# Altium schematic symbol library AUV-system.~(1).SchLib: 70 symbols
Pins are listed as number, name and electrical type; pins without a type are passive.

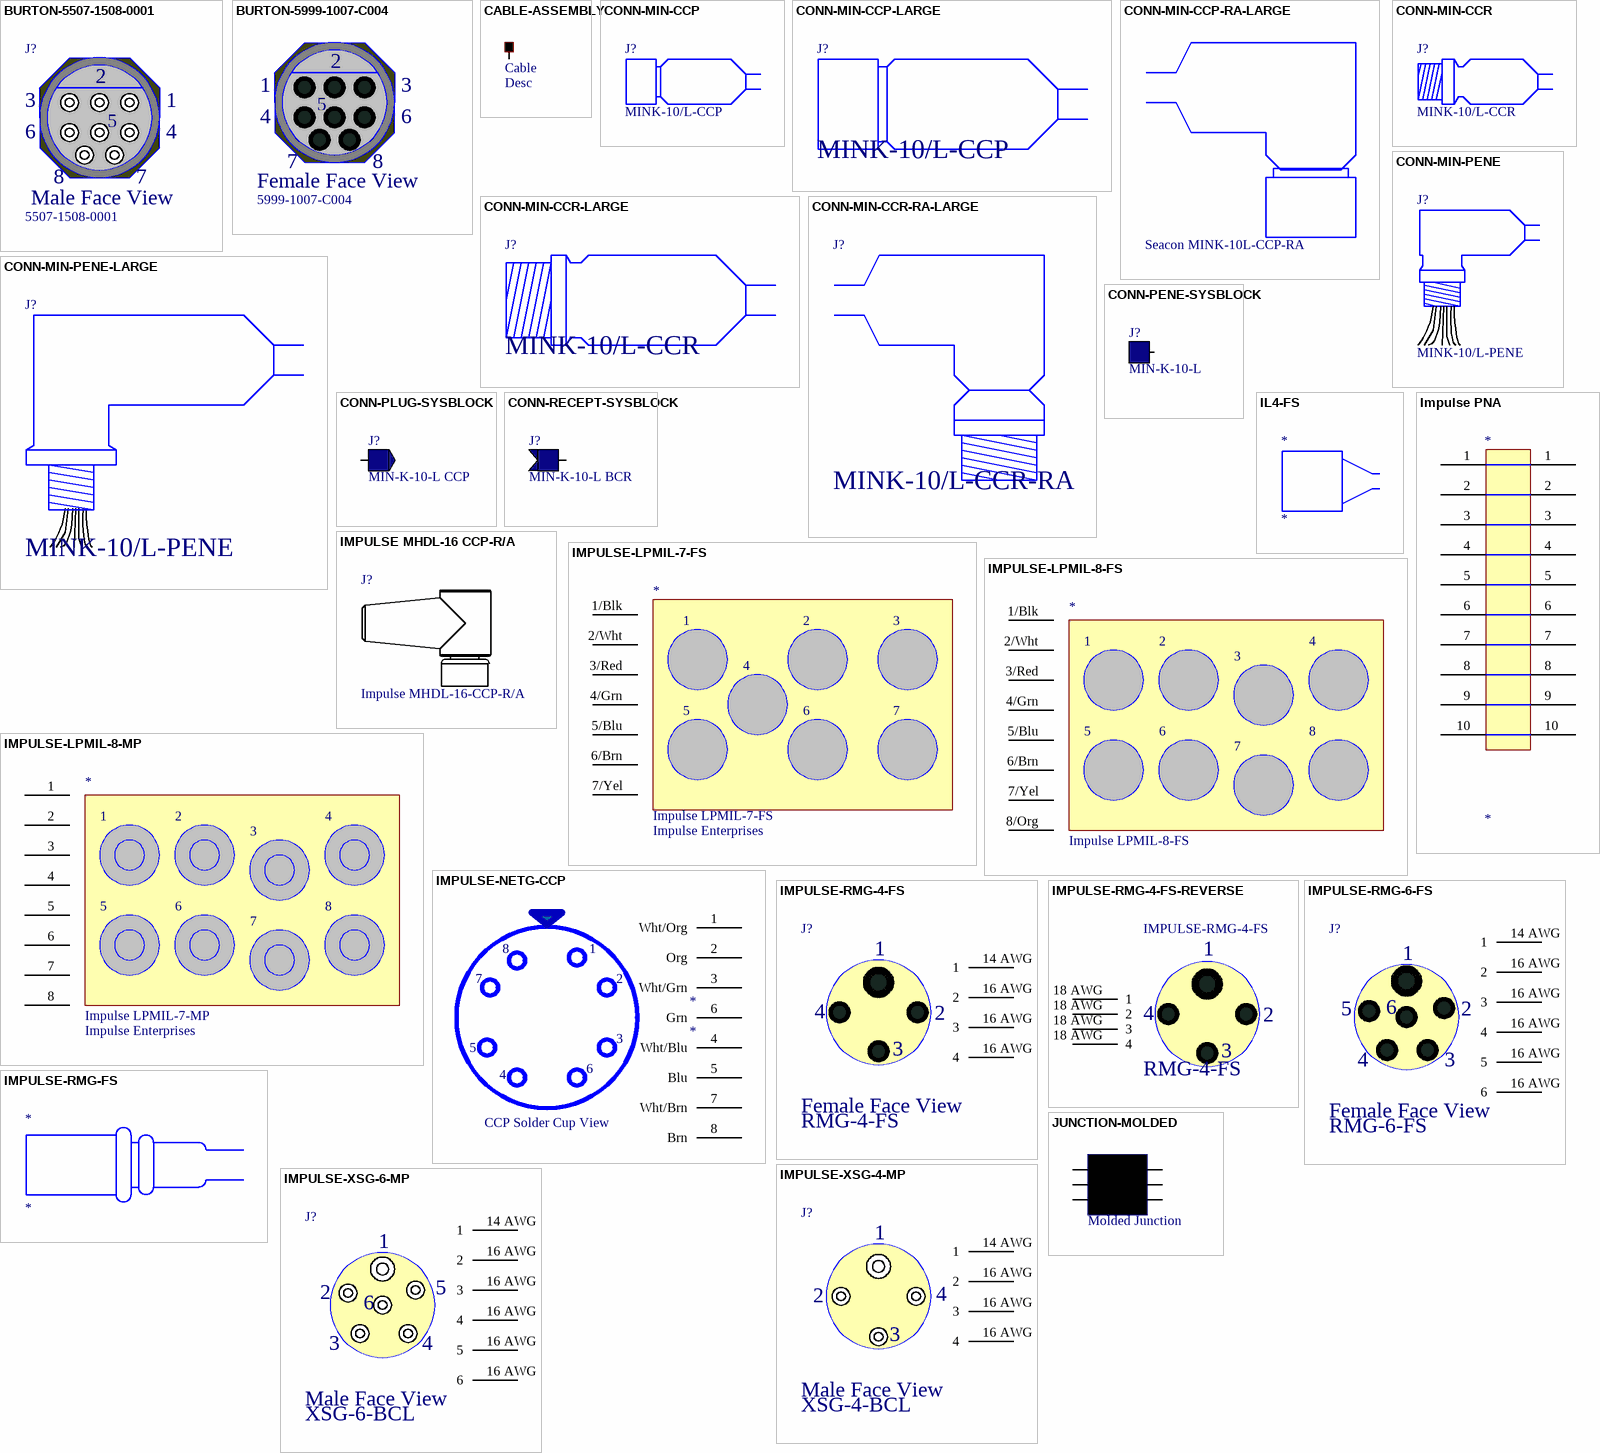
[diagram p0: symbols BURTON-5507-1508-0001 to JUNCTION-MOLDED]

## BURTON-5507-1508-0001
designator J?, comment 5507-1508-0001
Burton 8 Pin Male BH Connector

## BURTON-5999-1007-C004
designator J?, comment 5999-1007-C004
Burton 8 Socket Female IL Connector

## CABLE-ASSEMBLY
designator J?, comment Cable  DescSheet: Desc
Cable Assembly
pins: 0 "Pointer"

## CONN-MIN-CCP
designator J?, comment MINK-10/L-CCP
Seacon MIN Connector CCP

## CONN-MIN-CCP-LARGE
designator J?, comment MINK-10/L-CCP
Seacon MIN Connector CCP

## CONN-MIN-CCP-RA-LARGE
designator *, comment Seacon MINK-10L-CCP-RA

## CONN-MIN-CCR
designator J?, comment MINK-10/L-CCR
Seacon MIN Connector CCR

## CONN-MIN-CCR-LARGE
designator J?, comment MINK-10/L-CCR
Seacon MIN Connector CCR

## CONN-MIN-CCR-RA-LARGE
designator J?, comment MINK-10/L-CCR-RA
Seacon MIN Connector CCR Right Angle

## CONN-MIN-PENE
designator J?, comment MINK-10/L-PENE
Seacon MIN Penetrator

## CONN-MIN-PENE-LARGE
designator J?, comment MINK-10/L-PENE
Seacon MIN Penetrator

## CONN-PENE-SYSBLOCK
designator J?, comment MIN-K-10-L
Pene Symbol; Manufacturer: Seacon
pins: 0

## CONN-PLUG-SYSBLOCK
designator J?, comment MIN-K-10-L CCP
Plug Symbol; Manufacturer: Seacon
pins: 0

## CONN-RECEPT-SYSBLOCK
designator J?, comment MIN-K-10-L BCR
Recept Symbol; Manufacturer: Seacon
pins: 0

## IL4-FS
designator *

## IMPULSE MHDL-16 CCP-R/A
designator J?, comment Impulse MHDL-16-CCP-R/A

## Impulse PNA
designator *
Impulse 1''-14 PNA SS R/A Mold w/ 12x#16 Insert
pins: 1, 1, 2, 2, 3, 3, 4, 4, 5, 5, 6, 6, 7, 7, 8, 8, 9, 9, 10, 10

## IMPULSE-LPMIL-7-FS
designator *, comment Impulse LPMIL-7-FS  Vendor: Impulse Enterprises
pins: 1/Blk, 2/Wht 2, 3/Red 3, 4/Grn 4, 5/Blu 5, 6/Brn 6, 7/Yel 7

## IMPULSE-LPMIL-8-FS
designator *, comment Impulse LPMIL-8-FS
Impulse-8-FS Connector
pins: 1/Blk, 2/Wht 2, 3/Red 3, 4/Grn 4, 5/Blu 5, 6/Brn 6, 7/Yel 7, 8/Org 8

## IMPULSE-LPMIL-8-MP
designator *, comment Impulse LPMIL-7-MP  Vendor: Impulse Enterprises
Impulse LPMIL-8-MP Connector
pins: 1, 2, 3, 4, 5, 6, 7, 8

## IMPULSE-NETG-CCP
designator *
pins: 1 Wht/Org, 2 Org, 3 Wht/Grn, 4 Wht/Blu, 5 Blu, 6 Grn, 7 Wht/Brn, 8 Brn

## IMPULSE-RMG-4-FS
designator J?, comment RMG-4-FS
Impulse RMG Connector
pins: 14 AWG 1, 16 AWG 2, 16 AWG 3, 16 AWG 4

## IMPULSE-RMG-4-FS-REVERSE
designator IMPULSE-RMG-4-FS, comment RMG-4-FS
pins: 18 AWG 1, 18 AWG 2, 18 AWG 3, 18 AWG 4

## IMPULSE-RMG-6-FS
designator J?, comment RMG-6-FS
Impulse RMG Connector
pins: 14 AWG 1, 16 AWG 2, 16 AWG 3, 16 AWG 4, 16 AWG 5, 16 AWG 6

## IMPULSE-RMG-FS
designator *

## IMPULSE-XSG-4-MP
designator J?, comment XSG-4-BCL
Impulse XSG Connector; ManufPartNo: XSG-4-MP
pins: 14 AWG 1, 16 AWG 2, 16 AWG 3, 16 AWG 4

## IMPULSE-XSG-6-MP
designator J?, comment XSG-6-BCL
Impulse XSG Connector; ManufPartNo: XSG-6-MP
pins: 14 AWG 1, 16 AWG 2, 16 AWG 3, 16 AWG 4, 16 AWG 5, 16 AWG 6

## JUNCTION-MOLDED
designator J?, comment Molded Junction
pins: 1, 2, 3, 4, 5, 6

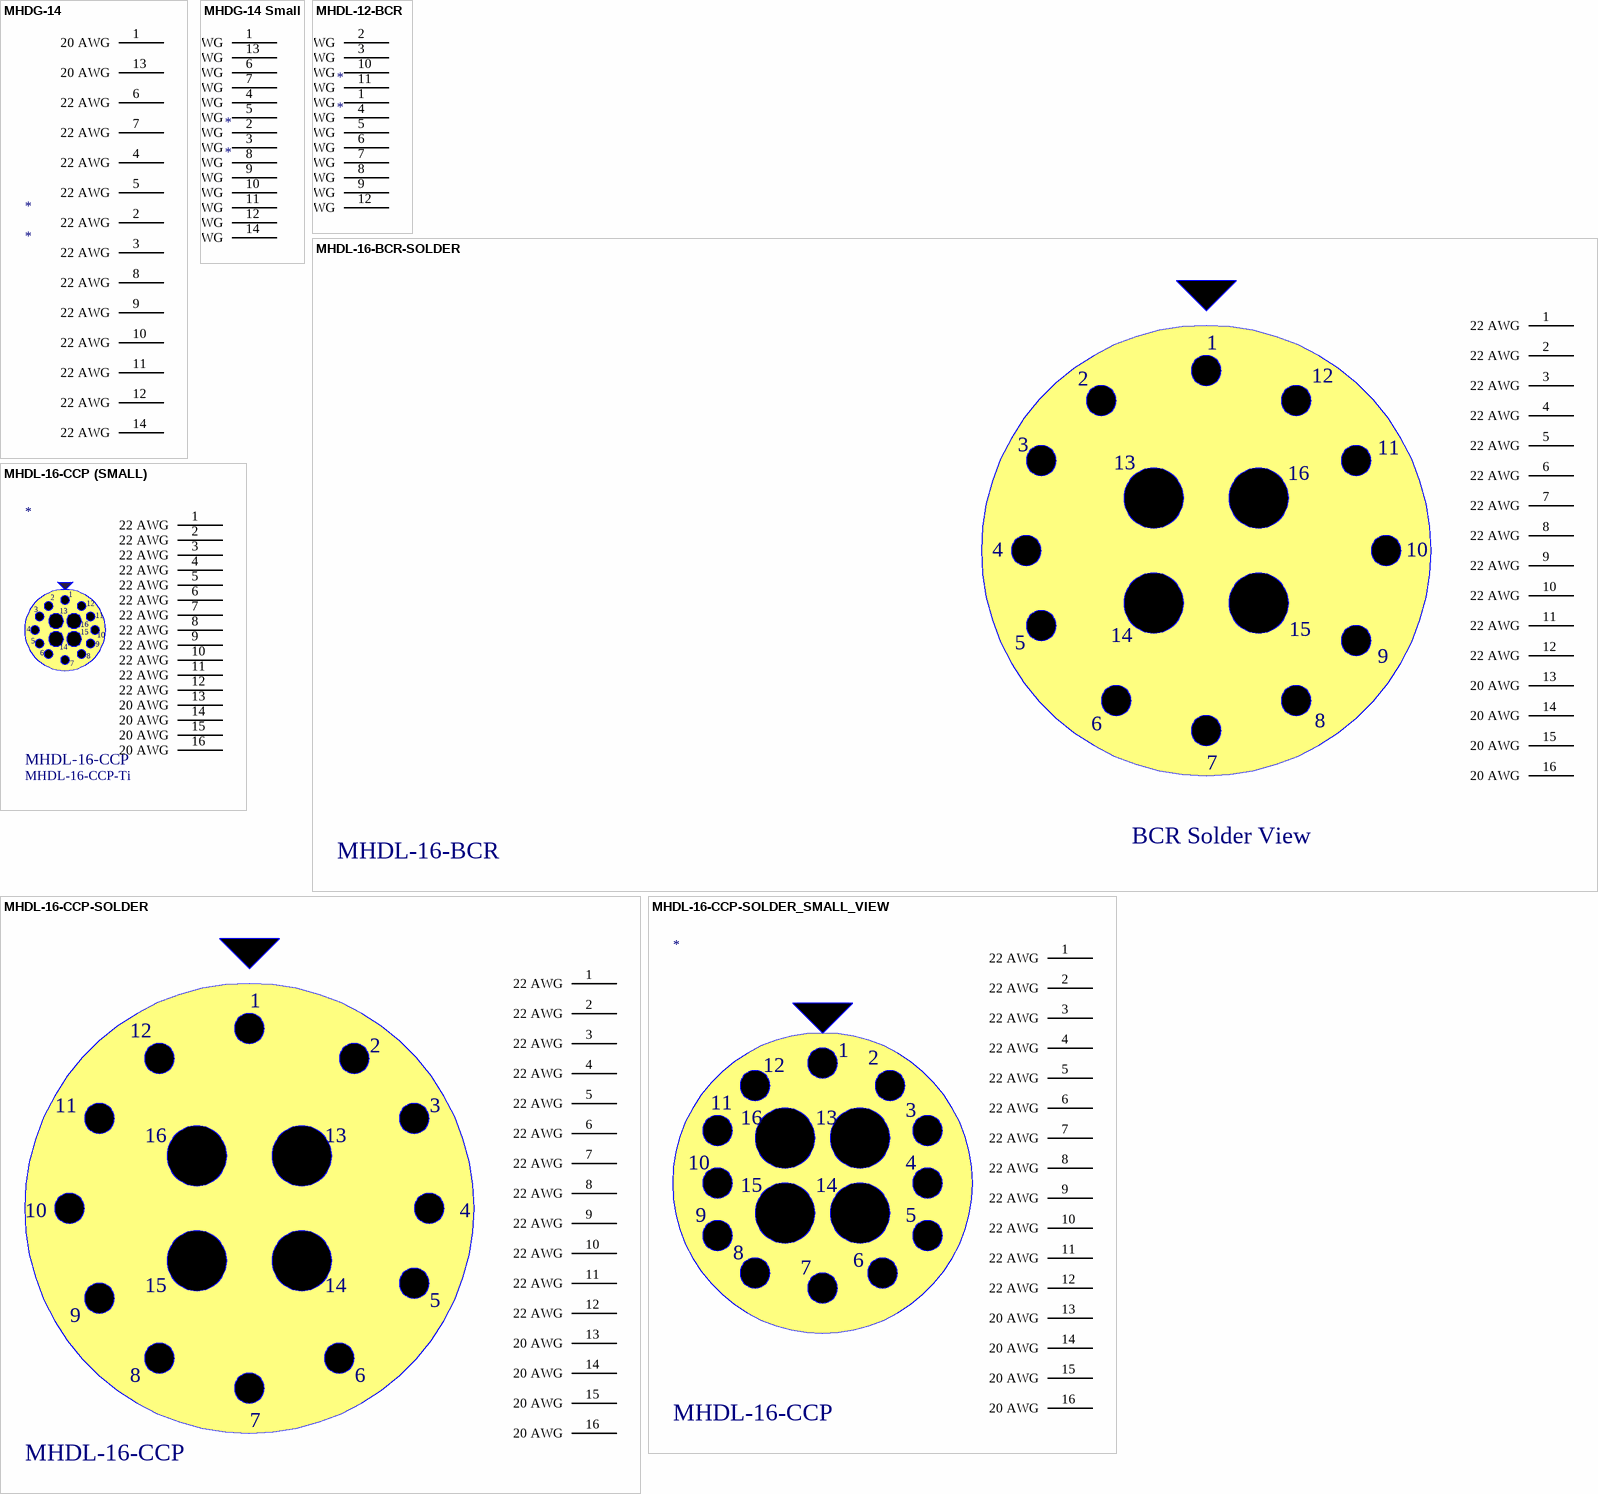
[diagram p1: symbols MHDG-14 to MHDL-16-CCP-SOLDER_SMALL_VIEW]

## MHDG-14
designator *
pins: 1 20 AWG, 2 22 AWG, 3 22 AWG, 4 22 AWG, 5 22 AWG, 6 22 AWG, 7 22 AWG, 8 22 AWG, 9 22 AWG, 10 22 AWG, 11 22 AWG, 12 22 AWG, 13 20 AWG, 14 22 AWG

## MHDG-14 Small
designator *
pins: 1 20 AWG, 2 22 AWG, 3 22 AWG, 4 22 AWG, 5 22 AWG, 6 22 AWG, 7 22 AWG, 8 22 AWG, 9 22 AWG, 10 22 AWG, 11 22 AWG, 12 22 AWG, 13 20 AWG, 14 22 AWG

## MHDL-12-BCR
designator *
Impulse MHDL12 BCR
pins: 1 22AWG, 2 16AWG, 3 16AWG, 4 22AWG, 5 22AWG, 6 22AWG, 7 22AWG, 8 22AWG, 9 22AWG, 10 16AWG, 11 16AWG, 12 22AWG

## MHDL-16-BCR-SOLDER
designator J?, comment MHDL-16-BCR
Impulse MHDL 16 BCR
pins: 1 22 AWG, 2 22 AWG, 3 22 AWG, 4 22 AWG, 5 22 AWG, 6 22 AWG, 7 22 AWG, 8 22 AWG, 9 22 AWG, 10 22 AWG, 11 22 AWG, 12 22 AWG, 13 20 AWG, 14 20 AWG, 15 20 AWG, 16 20 AWG

## MHDL-16-CCP (SMALL)
designator *, comment MHDL-16-CCP  ManufPartNo: MHDL-16-CCP-Ti
Impulse MHDL-16-CCP molded to C/F Falmat Cable
pins: 1 22 AWG, 2 22 AWG, 3 22 AWG, 4 22 AWG, 5 22 AWG, 6 22 AWG, 7 22 AWG, 8 22 AWG, 9 22 AWG, 10 22 AWG, 11 22 AWG, 12 22 AWG, 13 20 AWG, 14 20 AWG, 15 20 AWG, 16 20 AWG

## MHDL-16-CCP-SOLDER
designator J?, comment MHDL-16-CCP
Impulse MHDL 16 CCP
pins: 1 22 AWG, 2 22 AWG, 3 22 AWG, 4 22 AWG, 5 22 AWG, 6 22 AWG, 7 22 AWG, 8 22 AWG, 9 22 AWG, 10 22 AWG, 11 22 AWG, 12 22 AWG, 13 20 AWG, 14 20 AWG, 15 20 AWG, 16 20 AWG

## MHDL-16-CCP-SOLDER_SMALL_VIEW
designator *, comment MHDL-16-CCP
pins: 1 22 AWG, 2 22 AWG, 3 22 AWG, 4 22 AWG, 5 22 AWG, 6 22 AWG, 7 22 AWG, 8 22 AWG, 9 22 AWG, 10 22 AWG, 11 22 AWG, 12 22 AWG, 13 20 AWG, 14 20 AWG, 15 20 AWG, 16 20 AWG

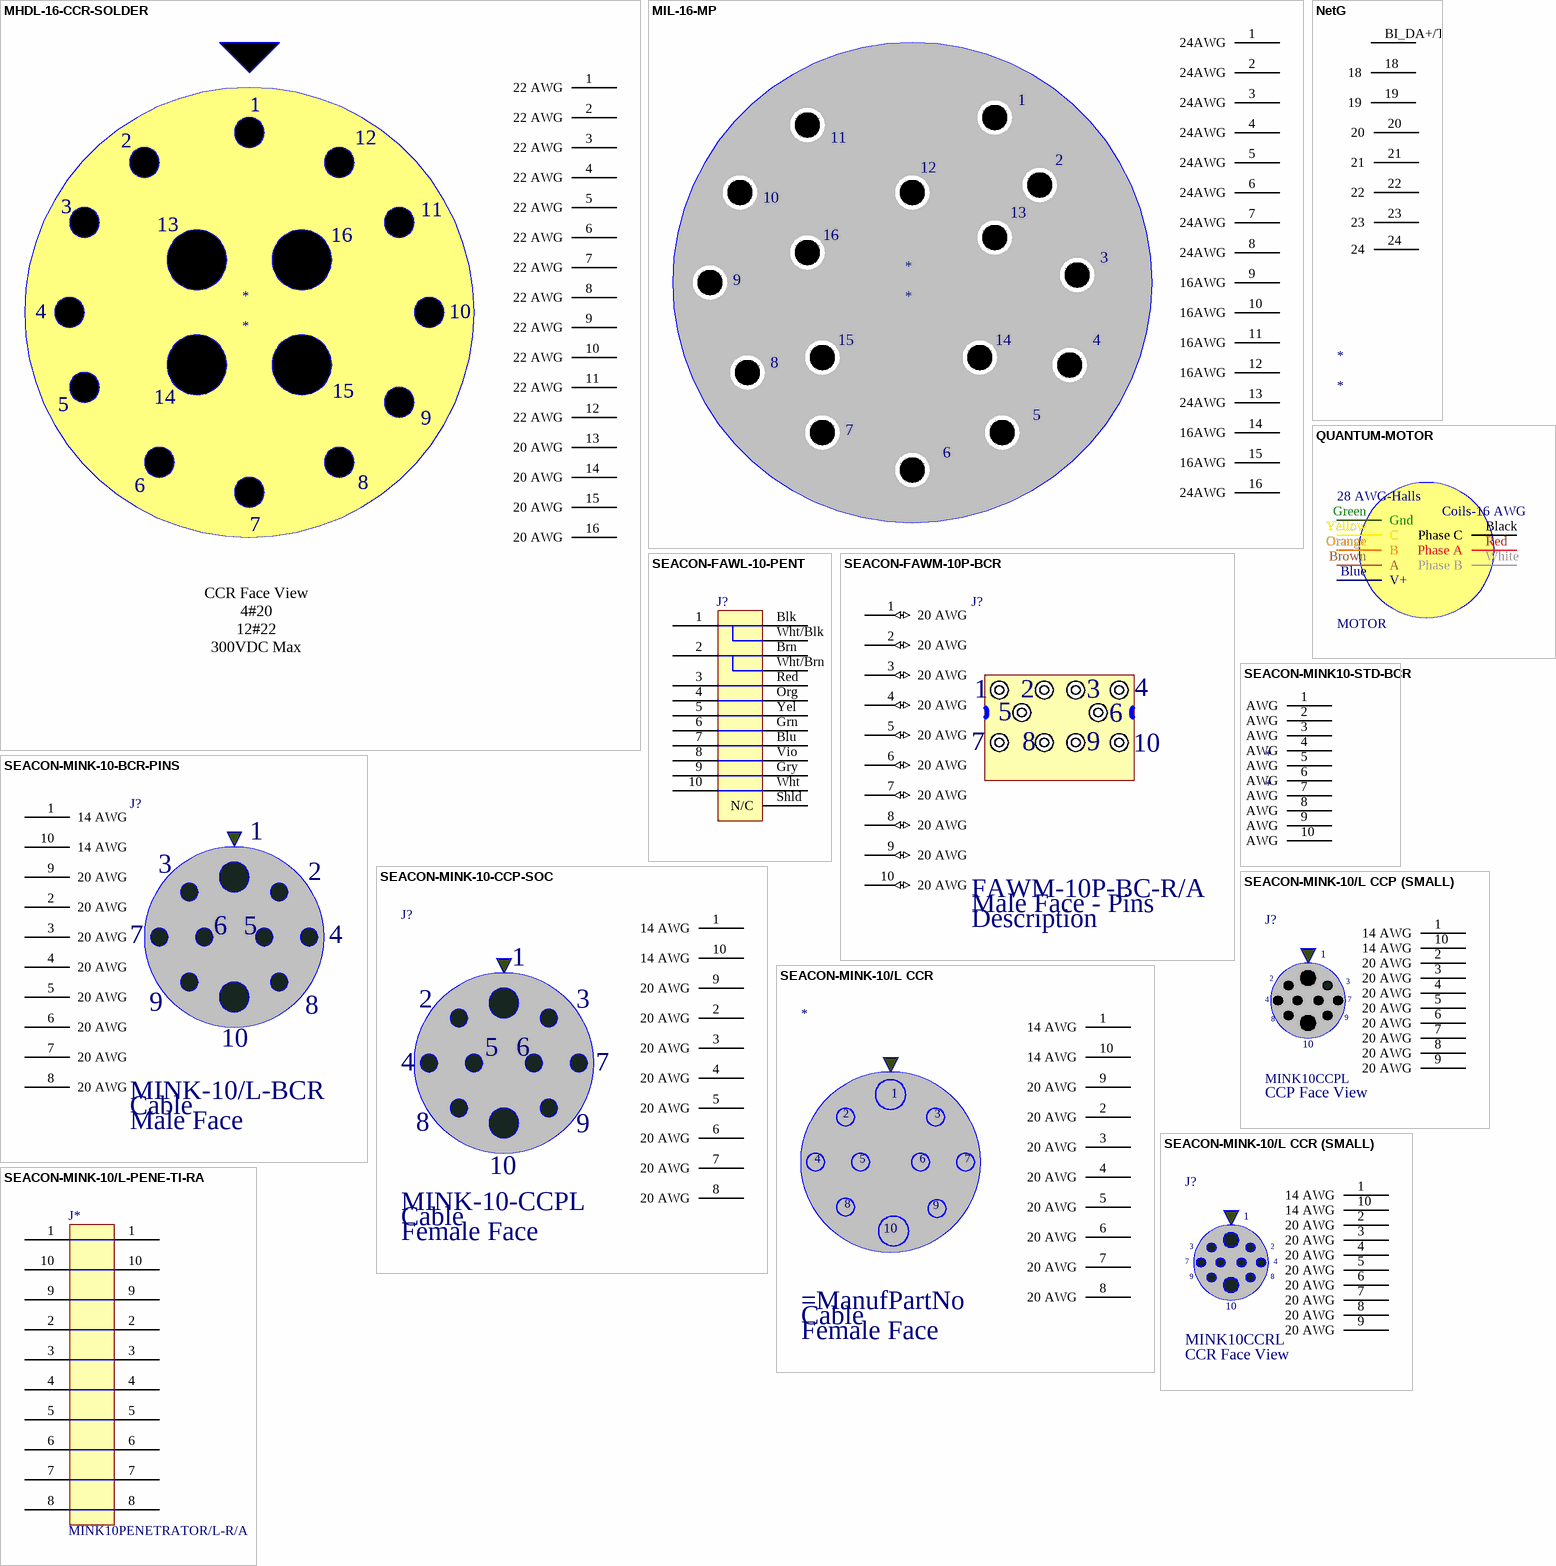
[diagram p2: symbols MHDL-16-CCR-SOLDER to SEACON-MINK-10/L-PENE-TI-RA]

## MHDL-16-CCR-SOLDER
designator *
pins: 1 22 AWG, 2 22 AWG, 3 22 AWG, 4 22 AWG, 5 22 AWG, 6 22 AWG, 7 22 AWG, 8 22 AWG, 9 22 AWG, 10 22 AWG, 11 22 AWG, 12 22 AWG, 13 20 AWG, 14 20 AWG, 15 20 AWG, 16 20 AWG

## MIL-16-MP
designator *
pins: 1 24AWG, 2 24AWG, 3 24AWG, 4 24AWG, 5 24AWG, 6 24AWG, 7 24AWG, 8 24AWG, 9 16AWG, 10 16AWG, 11 16AWG, 12 16AWG, 13 24AWG, 14 16AWG, 15 16AWG, 16 24AWG

## NetG
designator *
pins: 18, 19, 20, 21, 22, 23, 24, BI_DA+/TX+

## QUANTUM-MOTOR
designator ?, comment MOTOR
Quantum Motor
pins: Black Phase C (power), Blue V+ (power), Brown A (power), Green Gnd (power), Orange B (power), Red Phase A (power), White Phase B (power), Yellow C (power)

## SEACON-FAWL-10-PENT
designator J?
FAWL-10 Penetrator Molded onto Falmat #9835 Cable; Manufacturer: Seacon; ManufPartNo: FAWL-10-PENT
pins: 1, 2, 3, 4, 5, 6, 7, 8, 9, 10, Blk, Blu, Brn, Grn, Gry, Org, Red, Shld N/C, Vio, Wht, Wht/Blk, Wht/Brn, Yel

## SEACON-FAWM-10P-BCR
designator J?, comment FAWM-10P-BC-R/A  View: Male Face - Pins  DescSheet: Description
Seacon FAWM-10P-BC-R/A Connector
pins: 1 20 AWG (io), 2 20 AWG (io), 3 20 AWG (io), 4 20 AWG (io), 5 20 AWG (io), 6 20 AWG (io), 7 20 AWG (io), 8 20 AWG (io), 9 20 AWG (io), 10 20 AWG (io)

## SEACON-MINK10-STD-BCR
designator *
Seacon MINK10 BCR Standard Length
pins: 1 20 AWG, 2 20 AWG, 3 20 AWG, 4 20 AWG, 5 20 AWG, 6 20 AWG, 7 20 AWG, 8 20 AWG, 9 20 AWG, 10 20 AWG

## SEACON-MINK-10-BCR-PINS
designator J?, comment MINK-10/L-BCR  DescSheet: Cable  View: Male Face
Seacon MINK-10/L-BCR Connector
pins: 1 14 AWG, 2 20 AWG, 3 20 AWG, 4 20 AWG, 5 20 AWG, 6 20 AWG, 7 20 AWG, 8 20 AWG, 9 20 AWG, 10 14 AWG

## SEACON-MINK-10-CCP-SOC
designator J?, comment MINK-10-CCPL  DescSheet: Cable  View: Female Face
Seacon MINK-10/L-CCP Connector
pins: 1 14 AWG, 2 20 AWG, 3 20 AWG, 4 20 AWG, 5 20 AWG, 6 20 AWG, 7 20 AWG, 8 20 AWG, 9 20 AWG, 10 14 AWG

## SEACON-MINK-10/L CCP (SMALL)
designator J?, comment View: CCP Face View  (hidden comment: MINK10CCPL)
Seacon MINK-10/L-CCP molded to C/F Falmat Cable
pins: 1 14 AWG, 2 20 AWG, 3 20 AWG, 4 20 AWG, 5 20 AWG, 6 20 AWG, 7 20 AWG, 8 20 AWG, 9 20 AWG, 10 14 AWG

## SEACON-MINK-10/L CCR
designator *  DescSheet: Cable  View: Female Face
pins: 1 14 AWG, 2 20 AWG, 3 20 AWG, 4 20 AWG, 5 20 AWG, 6 20 AWG, 7 20 AWG, 8 20 AWG, 9 20 AWG, 10 14 AWG

## SEACON-MINK-10/L CCR (SMALL)
designator J?, comment MINK10CCRL  View: CCR Face View
Seacon MINK-10/L-CCR Molded to C/F Falmat Cable
pins: 1 14 AWG, 2 20 AWG, 3 20 AWG, 4 20 AWG, 5 20 AWG, 6 20 AWG, 7 20 AWG, 8 20 AWG, 9 20 AWG, 10 14 AWG

## SEACON-MINK-10/L-PENE-TI-RA
designator J*, comment MINK10PENETRATOR/L-R/A
Seacon MINK-10/L Penetrator w/ Right Angle Mold (Large View); Manufacturer: Seaconn
pins: 1, 1, 2, 2, 3, 3, 4, 4, 5, 5, 6, 6, 7, 7, 8, 8, 9, 9, 10, 10

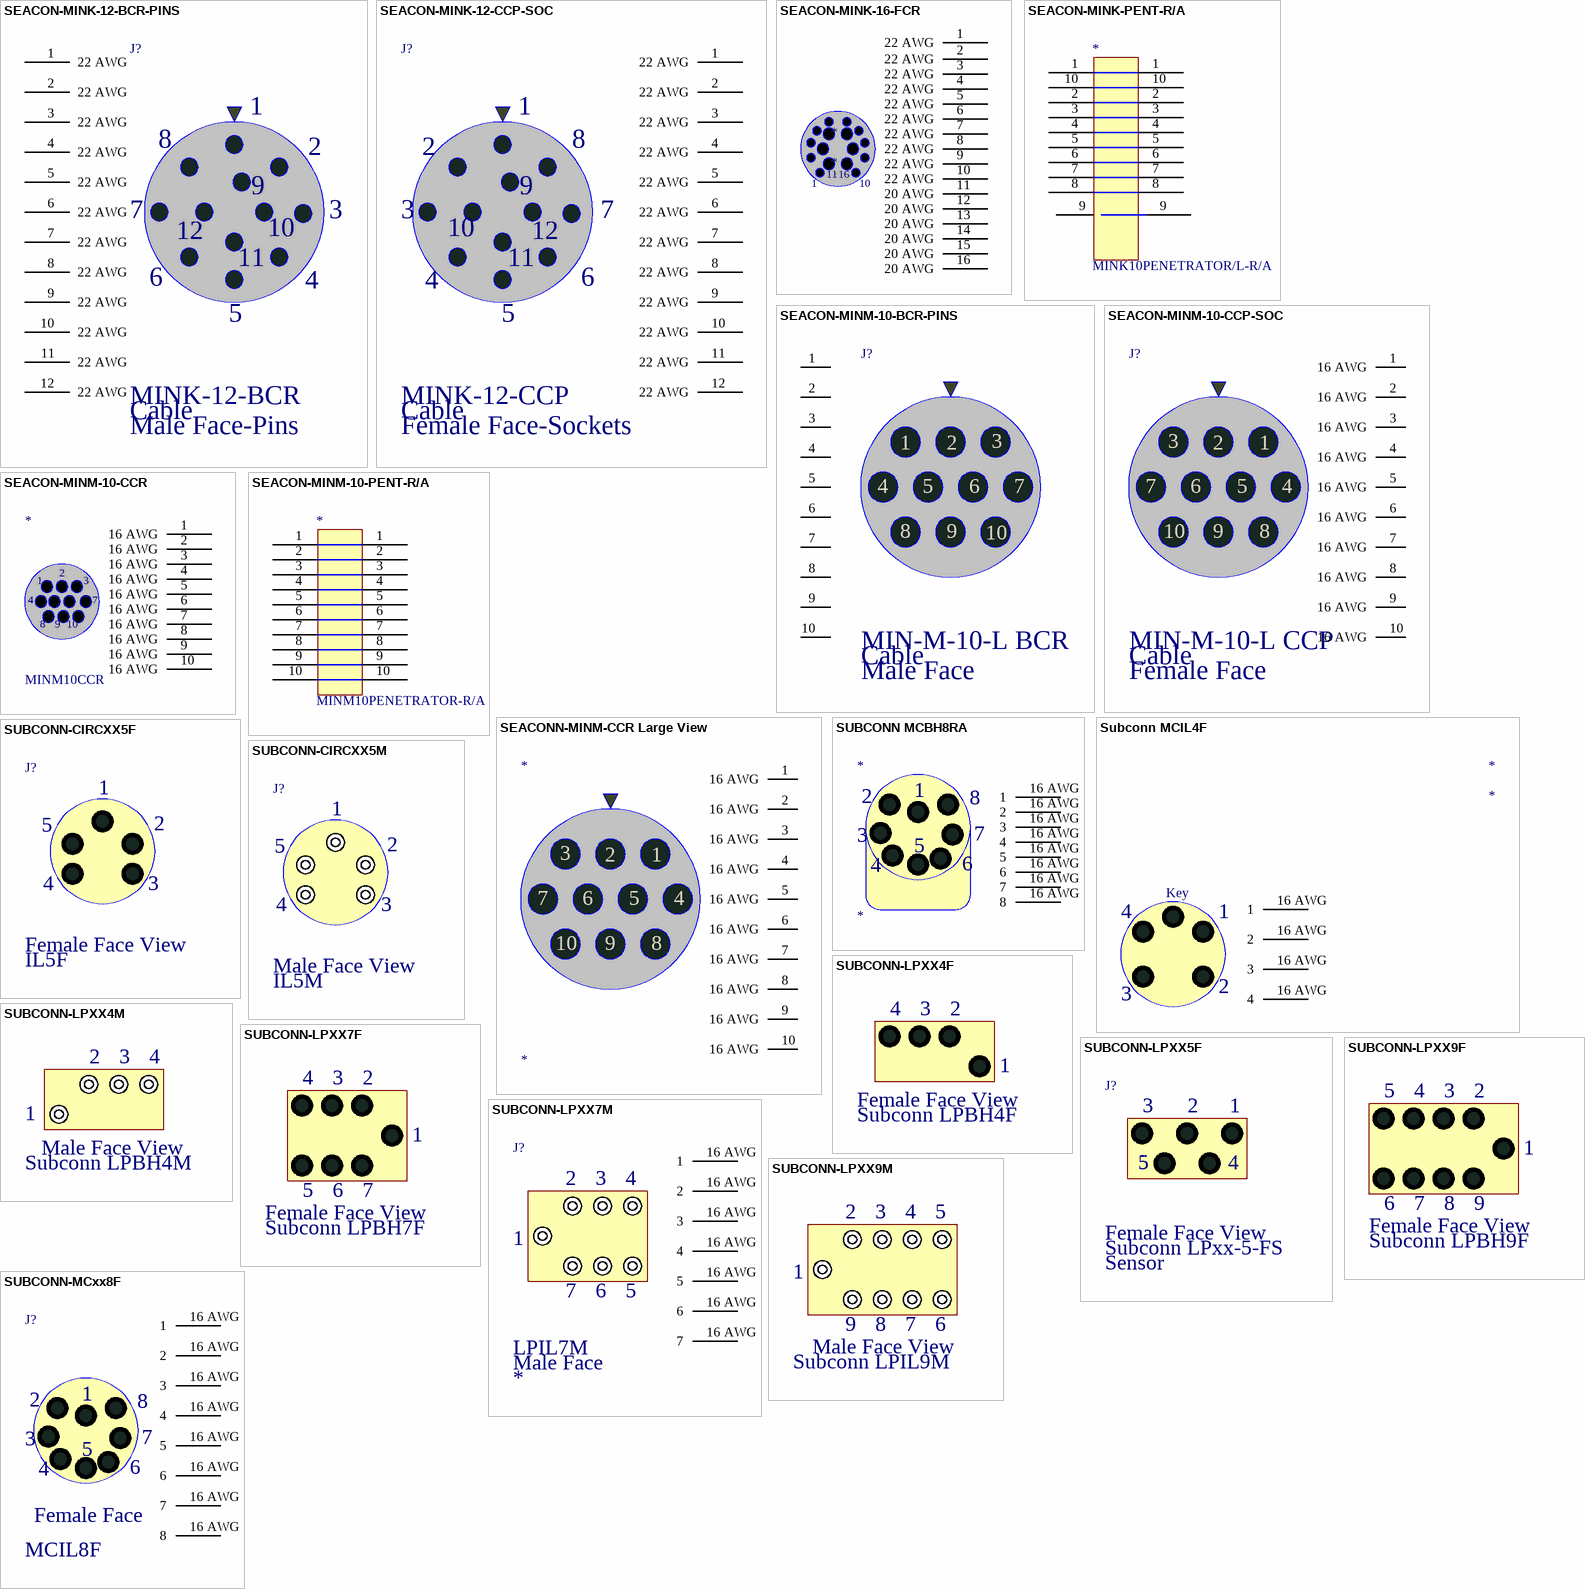
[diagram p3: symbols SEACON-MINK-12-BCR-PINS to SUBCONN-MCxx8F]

## SEACON-MINK-12-BCR-PINS
designator J?, comment MINK-12-BCR  DescSheet: Cable  View: Male Face-Pins
Seacon MINK-12-BCR Connector
pins: 1 22 AWG, 2 22 AWG, 3 22 AWG, 4 22 AWG, 5 22 AWG, 6 22 AWG, 7 22 AWG, 8 22 AWG, 9 22 AWG, 10 22 AWG, 11 22 AWG, 12 22 AWG

## SEACON-MINK-12-CCP-SOC
designator J?, comment MINK-12-CCP  DescSheet: Cable  View: Female Face-Sockets
Seacon MINK-12-CCP Connector
pins: 1 22 AWG, 2 22 AWG, 3 22 AWG, 4 22 AWG, 5 22 AWG, 6 22 AWG, 7 22 AWG, 8 22 AWG, 9 22 AWG, 10 22 AWG, 11 22 AWG, 12 22 AWG

## SEACON-MINK-16-FCR
designator *
Seacon MINK-16 FCR
pins: 1 22 AWG, 2 22 AWG, 3 22 AWG, 4 22 AWG, 5 22 AWG, 6 22 AWG, 7 22 AWG, 8 22 AWG, 9 22 AWG, 10 22 AWG, 11 20 AWG, 12 20 AWG, 13 20 AWG, 14 20 AWG, 15 20 AWG, 16 20 AWG

## SEACON-MINK-PENT-R/A
designator *, comment MINK10PENETRATOR/L-R/A
Seacon MINK-10/L Penetrator w/ Right Angle Mold
pins: 1, 1, 2, 2, 3, 3, 4, 4, 5, 5, 6, 6, 7, 7, 8, 8, 9, 9, 10, 10

## SEACON-MINM-10-BCR-PINS
designator J?, comment MIN-M-10-L BCR  DescSheet: Cable  View: Male Face
Seacon MINM-10/L-BCR Connector
pins: 1, 2, 3, 4, 5, 6, 7, 8, 9, 10

## SEACON-MINM-10-CCP-SOC
designator J?, comment MIN-M-10-L CCP  DescSheet: Cable  View: Female Face
Seacon MINM-10/L-CCP Connector
pins: 1 16 AWG, 2 16 AWG, 3 16 AWG, 4 16 AWG, 5 16 AWG, 6 16 AWG, 7 16 AWG, 8 16 AWG, 9 16 AWG, 10 16 AWG

## SEACON-MINM-10-CCR
designator *, comment MINM10CCR
Seacon MINM-10-CCR molded to 10x16AWG SO Cable
pins: 1 16 AWG, 2 16 AWG, 3 16 AWG, 4 16 AWG, 5 16 AWG, 6 16 AWG, 7 16 AWG, 8 16 AWG, 9 16 AWG, 10 16 AWG

## SEACON-MINM-10-PENT-R/A
designator *, comment MINM10PENETRATOR-R/A
Seacon MINM-10-PENT-R/A molded to C/F Falmat Cable; Manufacturer: Seaconn
pins: 1, 1, 2, 2, 3, 3, 4, 4, 5, 5, 6, 6, 7, 7, 8, 8, 9, 9, 10, 10

## SEACONN-MINM-CCR Large View
designator *
pins: 1 16 AWG, 2 16 AWG, 3 16 AWG, 4 16 AWG, 5 16 AWG, 6 16 AWG, 7 16 AWG, 8 16 AWG, 9 16 AWG, 10 16 AWG

## SUBCONN MCBH8RA
designator *
Subconn MCBH8F Right Angle Penetrator
pins: 16 AWG 1, 16 AWG 2, 16 AWG 3, 16 AWG 4, 16 AWG 5, 16 AWG 6, 16 AWG 7, 16 AWG 8

## Subconn MCIL4F
designator *
Subconn MCIL4F Connector
pins: 16 AWG 1, 16 AWG 2, 16 AWG 3, 16 AWG 4

## SUBCONN-CIRCXX5F
designator J?, comment IL5F
Subconn IL5F Connector

## SUBCONN-CIRCXX5M
designator J?, comment IL5M
Subconn IL5M Connector

## SUBCONN-LPXX4F
designator J?, comment DescSheet: Subconn LPBH4F  (hidden comment: LPXX4F)
Subconn LPxx4F Connector; DescSheet: Subconn LPIL4F

## SUBCONN-LPXX4M
designator J?, comment DescSheet: Subconn LPBH4M  (hidden comment: LPXX4M)
Subconn LPxx4M Connector; DescSheet: Subconn LPIL4M

## SUBCONN-LPXX5F
designator J?, comment Subconn LPxx-5-FS  DescSheet: Sensor
Subconn LPxx5F Connector

## SUBCONN-LPXX7F
designator J?, comment DescSheet: Subconn LPBH7F  (hidden comment: LPXX7F)
Subconn LPxx7F Connector; DescSheet: Subconn LPIL7F

## SUBCONN-LPXX7M
designator J?, comment LPIL7M  View: Male Face
Subconn LPxx7M Connector
pins: 16 AWG 1, 16 AWG 2, 16 AWG 3, 16 AWG 4, 16 AWG 5, 16 AWG 6, 16 AWG 7

## SUBCONN-LPXX9F
designator J?, comment DescSheet: Subconn LPBH9F  (hidden comment: LPXX9F)
Subconn LPxx9F Connector; DescSheet: Subconn LPIL9F

## SUBCONN-LPXX9M
designator J?, comment DescSheet: Subconn LPIL9M  (hidden comment: LPXX9M)
Subconn LPxx9F Connector; DescSheet: Subconn LPBH9M

## SUBCONN-MCxx8F
designator J?, comment MCIL8F  View: Female Face
Subconn MCIL8F Connector
pins: 16 AWG 1, 16 AWG 2, 16 AWG 3, 16 AWG 4, 16 AWG 5, 16 AWG 6, 16 AWG 7, 16 AWG 8

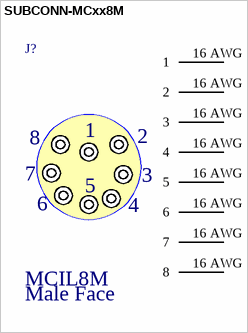
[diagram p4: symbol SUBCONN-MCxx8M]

## SUBCONN-MCxx8M
designator J?, comment MCIL8M  View: Male Face
Subconn MCIL8M Connector
pins: 16 AWG 1, 16 AWG 2, 16 AWG 3, 16 AWG 4, 16 AWG 5, 16 AWG 6, 16 AWG 7, 16 AWG 8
